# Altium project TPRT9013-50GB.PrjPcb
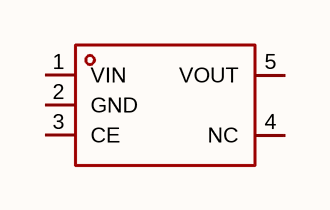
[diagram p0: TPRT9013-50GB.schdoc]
1 sheet, 1 parts. Net scope: global (net labels, ports and power ports of the same name join across sheets).

## Sheet TPRT9013-50GB.schdoc
size 127 x 101 mm

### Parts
U?  tprt9013-50gb  [SOT-23-5_L2.9-W1.6-P0.95-LS2.8-BR]  (value not drawn)

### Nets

Not connected (* = marked no-connect by the designer): U? 1(VIN) 2(GND) 3(CE) 4(NC) 5(VOUT)

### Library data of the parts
U? = tprt9013-50gb: 输出极性:正极;工作电压:7V;输出电压:5V;输出电流:500mA;电源纹波抑制比(PSRR):70dB@(1kHz);输出类型:固定;; Manufacturer: TECH PUBLIC(台舟); AddInBom: yes; ModelId: 7ba65df16e7b4570af156e925f9c37fe; ModelTransform: 114.173,114.173,0,90,0,0,0,0,0; Output Configuration: 正极; Voltage - Supply: 7V; Output Voltage: 5V; Output Current: 500mA; Voltage Dropout: 100mV@(100mA)；300mV@(200mA); standby current: 60uA; Noise: 50uVrms; Output Type: 固定; Number of Outputs: 1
